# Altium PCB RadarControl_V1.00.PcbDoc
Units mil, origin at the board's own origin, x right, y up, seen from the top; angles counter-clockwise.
Board outline 6000 x 4000 mil, 2 copper layers (Top Layer, Bottom Layer); 76 components, 67 nets, 269 pads, 123 vias.
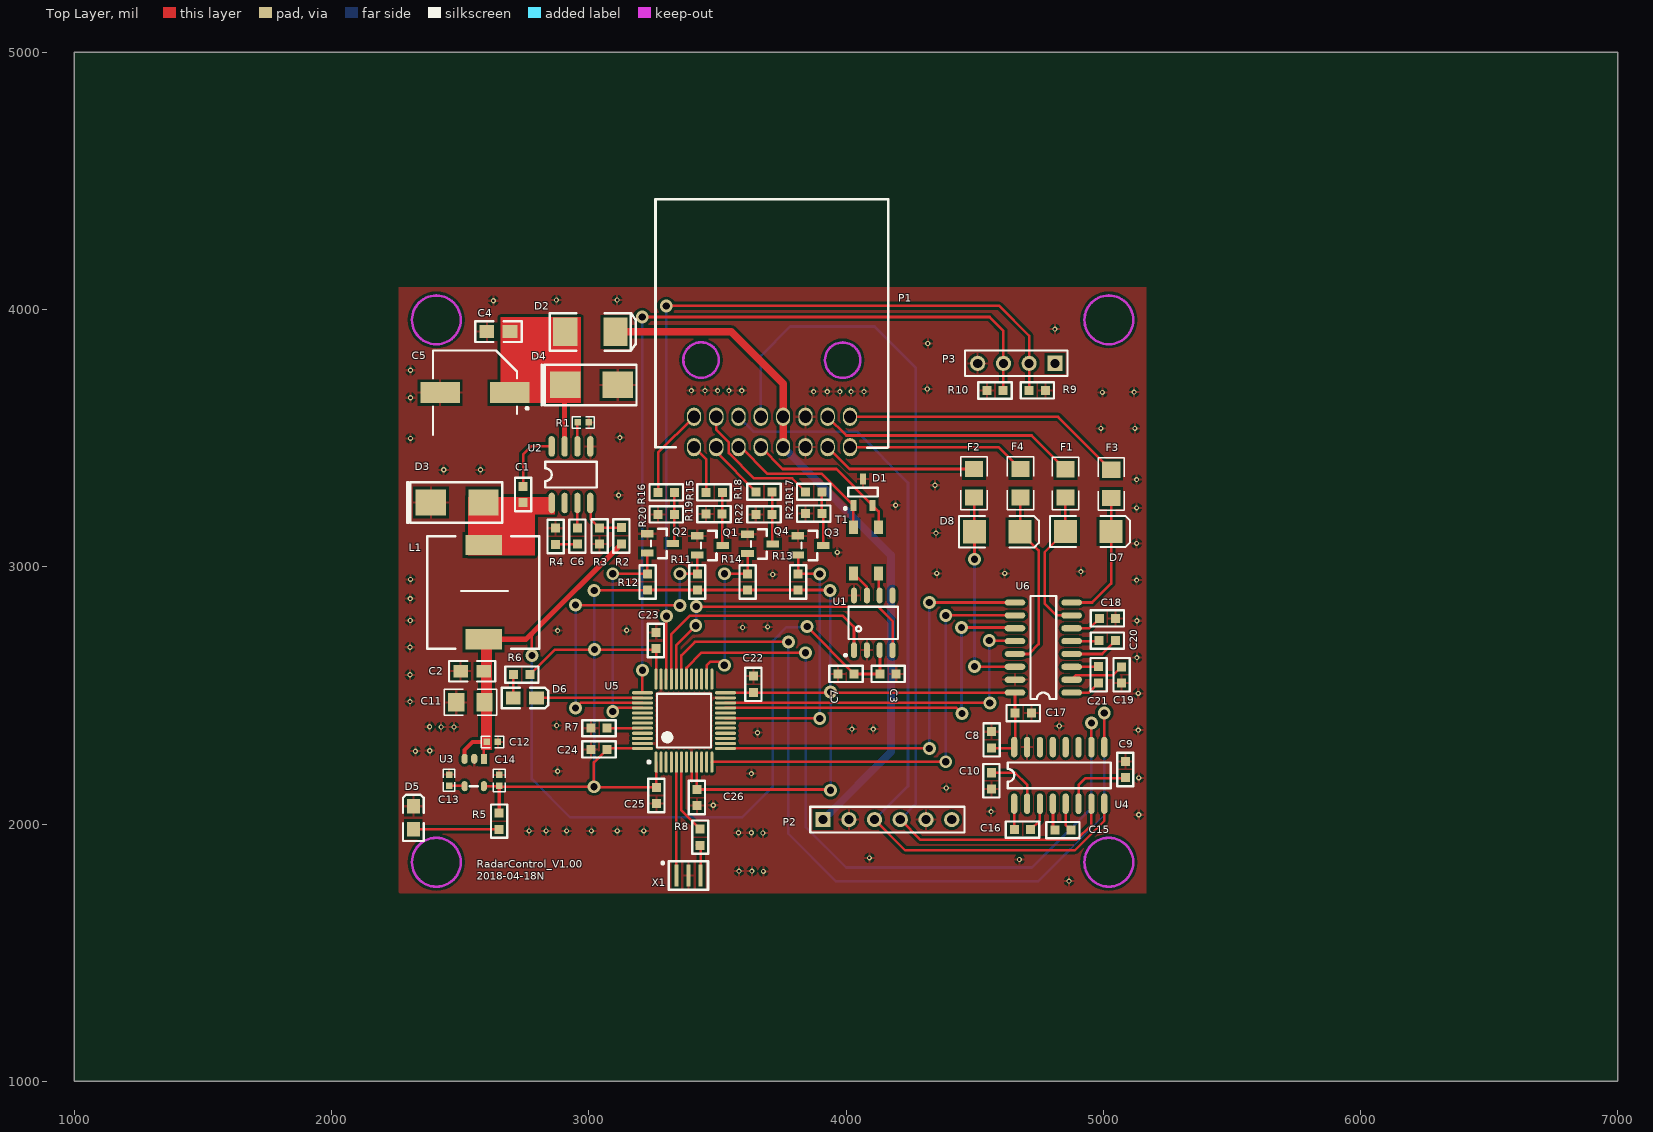
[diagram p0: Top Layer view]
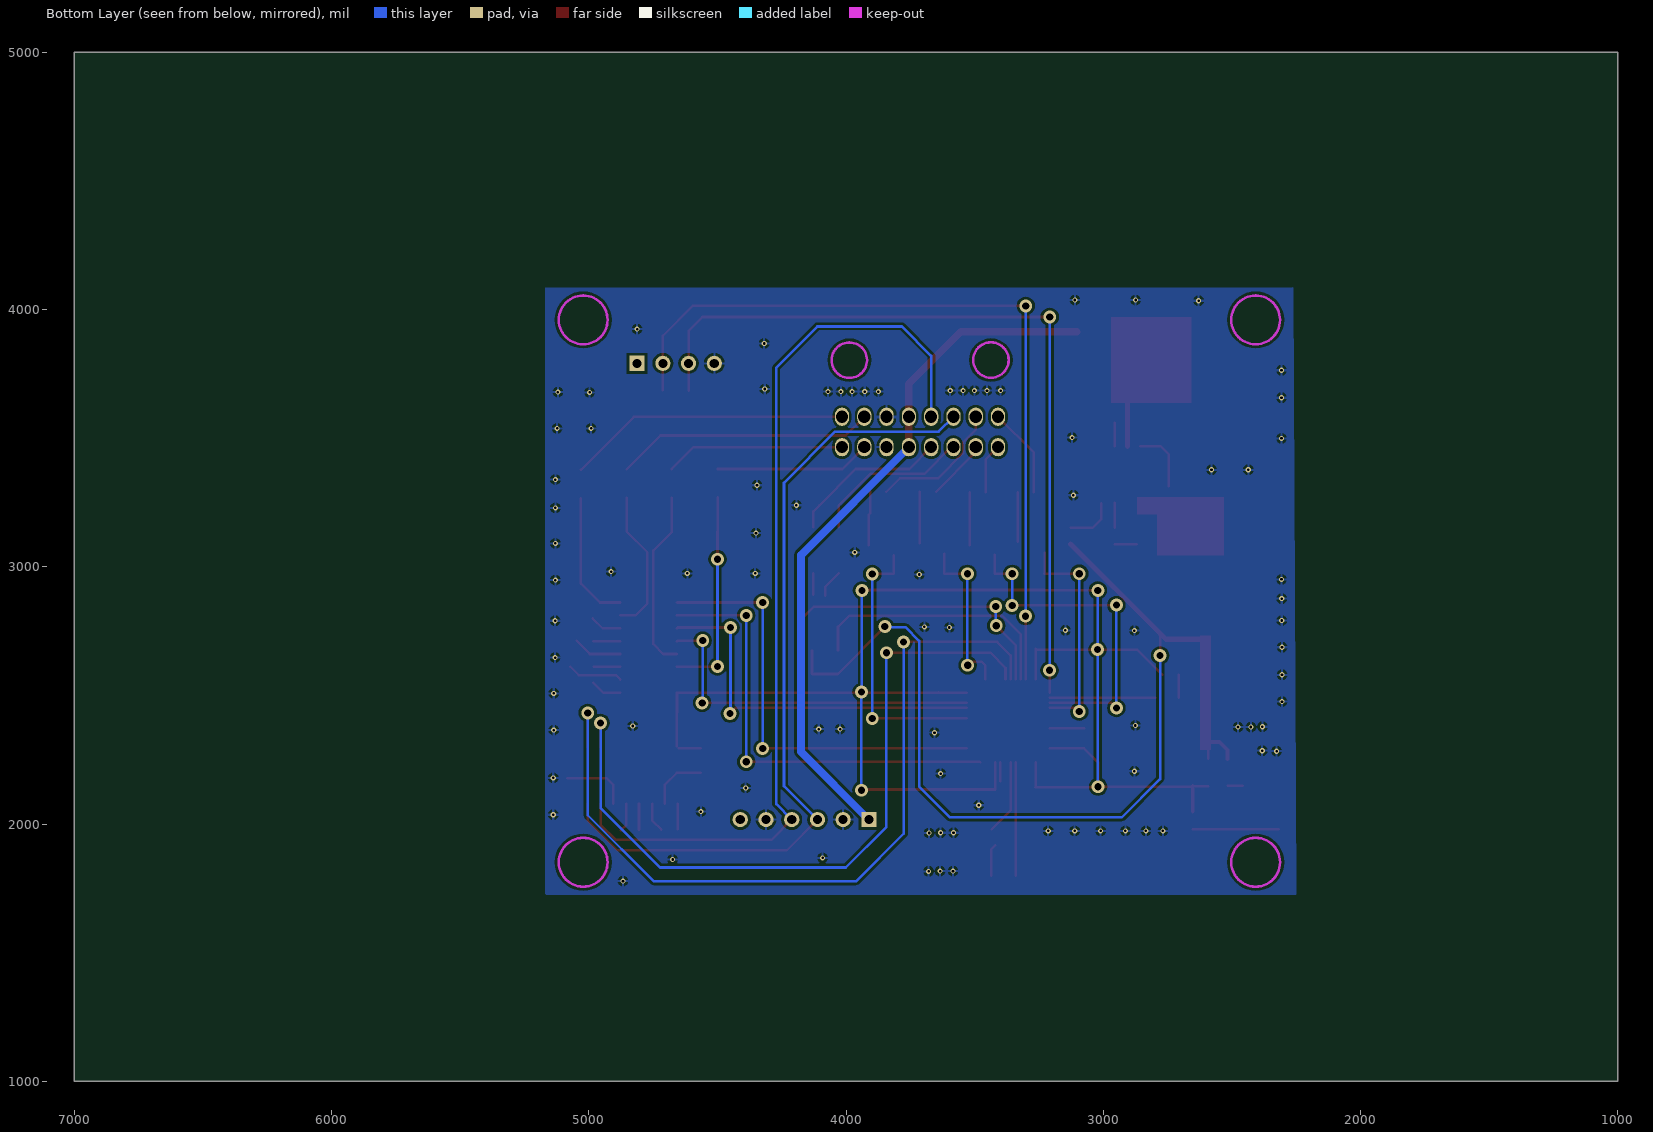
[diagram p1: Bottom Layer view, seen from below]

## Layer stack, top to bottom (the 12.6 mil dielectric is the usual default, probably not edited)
Top Solder: solder mask 0.4, Solder Resist, Dk 3.5
Top Layer: signal copper 1.4
Dielectric 1: dielectric 12.6, FR-4, Dk 4.8
Bottom Layer: signal copper 1.4
Bottom Solder: solder mask 0.4, Solder Resist, Dk 3.5

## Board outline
1000,1000 7000,1000 7000,5000 1000,5000

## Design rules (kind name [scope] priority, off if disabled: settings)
Clearance [All] p1: gap=5
MinimumSolderMaskSliver [All] p1 off: minsoldermaskwidth=10
PolygonConnect [All] p1: connectstyle=Relief reliefconductorwidth=10 reliefentries=4 polygonreliefangle="90 Angle" airgapwidth=10
RoutingVias [All] p1: holewidth=28 width=50 viastyle="Through Hole" minholewidth=28 minwidth=50 maxholewidth=28 maxwidth=50
SilkToSilkClearance [All] p1 off: silktosilkclearance=10
SilkToSolderMaskClearance [IsPad] p1 off: minsilkscreentomaskgap=10 clearancetoexposedcopper=TRUE
SolderMaskExpansion [All] p1: expansion=4
Width [All] p1: maxlimit=30 minlimit=10 preferedwidth=10
27 further rules are at their usual default settings.

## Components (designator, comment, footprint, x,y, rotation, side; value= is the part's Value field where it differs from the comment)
C1 "100nF" 0603 2749,3220 r180 top
C2 "22uF" 0805 2547,2594 r0 top
C3 "100nF" 0603 4225,2588 r270 top
C4 "10uF" 0805 2649,3914 r0 top
C5 "47uF" cap_pol_8*10.2 2558,3677 r180 top
C6 "150pF" 0603 2960,3058 r180 top
C7 "22uF/10V" 0603 3939,2579 r90 top
C8 "100nf" 0603 4570,2266 r180 top
C9 "100nf" 0603 5090,2151 r180 top
C10 "100nf" 0603 4561,2229 r0 top
C11 "22uF" 1206 2595,2473 r180 top
C12 "100nF" 0402 2519,2315 r90 top
C13 "NULL" 0402 2461,2064 r180 top
C14 "1uF" 0402 2656,2063 r180 top
C15 "100nf" 0603 4782,1972 r90 top
C16 "100nf" 0603 4625,1974 r90 top
C17 "100nf" 0603 4628,2427 r90 top
C18 "100nf" 0603 4954.95,2795 r90 top
C19 "100nf" 0603 5067,2641.05 r0 top
C20 "100nf" 0603 5077,2717 r270 top
C21 "100nf" 0603 4986,2519 r180 top
C22 "100nF" 0603 3644,2482 r180 top
C23 "100nF" 0603 3265,2652 r180 top
C24 "100nF" 0603 3101.05,2294 r270 top
C25 "100nF" 0603 3259,2172 r0 top
C26 "1uF" 0603 3416,2164 r0 top
D1 "PESD2CAN" SOT23 4068,3291 r90 top
D2 "1N4007" 6032_pol 3004,3915 r0 top
D3 "B290-13-F" B290 2386,3250 r0 top
D4 "SMAJ36CA" B290 2908,3707 r0 top
D5 "LED_POWER" 0805-LED 2318,2024 r90 top
D6 "LED0" 0805-LED 2752,2490 r0 top
D7 "SMBJ18CA" SMB 4942,3137 r0 top
D8 "SMBJ18CA" SMB 4588,3136 r0 top
F1 "SMD1206-010" 1206 4853,3379 r270 top
F2 "SMD1206-010" 1206 4498,3380 r270 top
F3 "SMD1206-010" 1206 5031,3377 r270 top
F4 "SMD1206-010" 1206 4678,3380 r270 top
L1 "22uH" 10*10Inductor 2591,2718 r0 top
P1 "1318382(16PIN)" "16pin 1318382" 4127,3483 r180 top
P2 "2.54MM-5PIN" HDR1X6 3911,2017 r0 top
P3 "2.54mm/4pin" HDR1X4 4811.97,3790.83 r180 top
Q1 "LMBT3904LT1G" LC-SOT-23(SOT-23-3) 3471,3083 r180 top
Q2 "LMBT3904LT1G" LC-SOT-23(SOT-23-3) 3277,3091 r180 top
Q3 "LMBT3904LT1G" LC-SOT-23(SOT-23-3) 3862,3083 r180 top
Q4 "LMBT3904LT1G" LC-SOT-23(SOT-23-3) 3666,3089 r180 top
R1 "200K" 0402 2872,3557 r90 top
R2 "205K" 0603 3131,3059 r180 top
R3 "40.2K" 0603 3038,3181 r0 top
R4 "100k" 0603 2875,3057 r180 top
R5 "510R" 0603 2647,2072 r0 top
R6 "2.2K" 0603 2801,2585 r270 top
R7 "10K" 0603 2979,2368 r90 top
R8 "100" 0603 3429,2010 r0 top
R9 "1K" 0603 4805,3690 r270 top
R10 "1K" 0603 4518,3681 r90 top
R11 "10K" 0603 3426,2880 r180 top
R12 "10K" 0603 3233,2880 r180 top
R13 "10K" 0603 3818,2880 r180 top
R14 "10K" 0603 3622,2880 r180 top
R15 "100k" 0603 3426.24,3284.75 r90 top
R16 "100k" 0603 3240.24,3284.75 r90 top
R17 "100k" 0603 3813.76,3287.25 r90 top
R18 "100k" 0603 3619.95,3287.25 r90 top
R19 "10K" 0603 3548.28,3208.75 r270 top
R20 "10K" 0603 3362.28,3208 r270 top
R21 "10K" 0603 3935.8,3211.25 r270 top
R22 "10K" 0603 3742,3208 r270 top
T1 "ACT45B-510-2P" ACT45B-510-2P 4127,2974 r90 top
U1 "TJA1050T" SO8 4105,2781 r90 top
U2 "MP2565DN" so-8 2856,3248 r90 top
U3 "RT9013-33GB" SOT-23-5 2553,2206 r180 top
U4 "SP3232EEN" SO-16 4654,2079 r90 top
U5 "STM32F103C8T6" STM-LQFP48_M 3370,2402 r90 top
U6 "SP3232EEN" SO-16 4877,2511 r180 top
X1 "8M smd" 8M 3340.47,1799.53 r0 top

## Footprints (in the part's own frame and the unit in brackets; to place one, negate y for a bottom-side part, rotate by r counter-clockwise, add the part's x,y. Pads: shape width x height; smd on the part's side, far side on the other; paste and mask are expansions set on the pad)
8M [mm]
  rect 0.4x2.2 smd: 1(0,0) 2(1.2,0) 3(2.4,0)
  silkscreen extent -1.45,-1.39 3.13,1.4
10*10Inductor [mm]
  rect 3.6x2 smd: 1(0,0) 2(0,9.3)
  silkscreen extent -5.55,-0.92 5.49,10.19
"16pin 1318382" [mm] "1318382"
  oval 1.4x1.8 hole 1.2: 1(2.835,-2.542) 2(5.035,-2.542) 3(7.235,-2.542) 4(9.435,-2.542) 5(11.635,-2.542) 6(13.835,-2.542) 7(16.035,-2.542) 8(18.235,-2.542) 9(2.835,0.458) 10(5.035,0.458) 11(7.235,0.458) 12(9.435,0.458) 13(11.635,0.458) 14(13.835,0.458) 15(16.035,0.458) 16(18.235,0.458)
  Keep-Out Layer circle w0.254: c3.556,-8.128 r1.75
  Keep-Out Layer circle w0.254: c17.535,-8.142 r1.75
  silkscreen extent -0.96,-24 22.04,0.51
0402 [mil]
  rect 25x25 smd: 1(3.98,-127.99) 2(3.98,-84.98)
  silkscreen extent -19,-150 26,-63
0603 [mil]
  rect 35x35 smd: 1(4.25,-92.76) 2(4.25,-29.76)
  silkscreen extent -27,-126 36,4
0805 [mil]
  rect 57x50 smd: 1(-45,0) 2(45,0)
  silkscreen extent -90,-40 90,40
0805-LED [mil]
  rect 57x50 smd: 1(-45,0) 2(45,0)
  silkscreen extent -90,-40 90,40
1206 [mm]
  rect 1.6x1.8 smd: 1(0,0) 2(2.8,0)
  silkscreen extent -1.2,-1.3 4,1.3
6032_pol [mm]
  rect 2.4x2.8 smd: 1(2.538,-0.041) 2(-2.422,-0.041)
  silkscreen extent -3.95,-1.89 4.53,1.81
ACT45B-510-2P [mm]
  rect 1.35x0.9 smd: 1(0,0) 2(4.55,0) 3(0,2.5) 4(4.55,2.5)
B290 [mm]
  rect 3x2.6 smd: 1(0,0) 2(5.2,0)
  silkscreen extent -2.34,-2 7.06,2
cap_pol_8*10.2 [mm]
  rect 3.9x2.05 smd: 1(-3.443,-0.001) 2(3.457,-0.001)
  silkscreen extent -5.27,-4.15 4.16,4.15
HDR1X4 [mm] "Connector; Header; 4 Position"
  rect 1.5x1.5 hole 0.9: 1(0,0)
  round 1.5 hole 0.9: 2(2.54,0) 3(5.08,0) 4(7.62,0)
  silkscreen extent -1.27,-1.27 8.89,1.27
HDR1X6 [mm] "Connector; Header; 6 Position"
  rect 1.5x1.5 hole 0.9: 1(0,0)
  round 1.5 hole 0.9: 2(2.54,0) 3(5.08,0) 4(7.62,0) 5(10.16,0) 6(12.7,0)
  silkscreen extent -1.27,-1.27 13.97,1.27
LC-SOT-23(SOT-23-3) [mm]
  rect 1.25x0.7 smd: 1(1.25,-0.95) 2(-1.25,0) 3(1.25,0.95)
  silkscreen extent -0.65,-1.46 0.9,1.46
SMB [mm] "DO-214-AA/SMB; 2 C-Bend Leads; Body 5.3 x 3.6 mm, inc. leads (LxW)"
  rect 2.3x2.3 smd: 1(-2.25,0) 2(2.25,0)
  silkscreen extent -3.8,-1.55 4.1,1.55
SO8 [mm]
  oval 1.55x0.6 smd: 1(-2.675,1.88) 2(-2.675,0.61) 3(-2.675,-0.66) 4(-2.675,-1.93) 5(2.725,-1.93) 6(2.725,-0.66) 7(2.725,0.61) 8(2.725,1.88)
  silkscreen extent -3.3,-2.48 1.63,2.85
so-8 [mil]
  oval 80x24 smd: 1(0,0) 2(0,-50) 3(0,-100) 4(0,-150) 5(220,-150) 6(220,-100) 7(220,-50) 8(220,0)
  silkscreen extent 60,-175 160,25
SO-16 [mil]
  oval 80x24 smd: 1(0,0) 2(0,-50) 3(0,-100) 4(0,-150) 5(0,-200) 6(0,-250) 7(0,-300) 8(0,-350) 9(220,-350) 10(220,-300) 11(220,-250) 12(220,-200) 13(220,-150) 14(220,-100) 15(220,-50) 16(220,0)
  silkscreen extent 60,-375 160,25
SOT23 [mm]
  rect 1.1x0.6 smd: 1(-1.325,1.001) 2(-1.325,-0.899) 3(1.275,0.051)
  silkscreen extent -1.75,-1.4 0.4,1.93
SOT-23-5 [mm]
  rect 0.6x1 smd: 1(-0.995,-1.201)
  oval 0.6x1 smd: 2(-0.045,-1.201) 3(0.905,-1.201) 4(0.905,1.499) 5(-0.995,1.499)
  silkscreen extent -0.4,1.5 0.4,1.5, body extent -1.5,-1.3 1.4,1.5, height 1.2
STM-LQFP48_M [mm] "QFP, 48-Leads, Body 7x7mm, Pitch 0.5mm, IPC Low Density"
  oval 2.1x0.3 smd: 1(-4.1,2.75) 2(-4.1,2.25) 3(-4.1,1.75) 4(-4.1,1.25) 5(-4.1,0.75) 6(-4.1,0.25) 7(-4.1,-0.25) 8(-4.1,-0.75) 9(-4.1,-1.25) 10(-4.1,-1.75) 11(-4.1,-2.25) 12(-4.1,-2.75) 25(4.1,-2.75) 26(4.1,-2.25) 27(4.1,-1.75) 28(4.1,-1.25) 29(4.1,-0.75) 30(4.1,-0.25) 31(4.1,0.25) 32(4.1,0.75) 33(4.1,1.25) 34(4.1,1.75) 35(4.1,2.25) 36(4.1,2.75)
  oval 0.3x2.1 smd: 13(-2.75,-4.1) 14(-2.25,-4.1) 15(-1.75,-4.1) 16(-1.25,-4.1) 17(-0.75,-4.1) 18(-0.25,-4.1) 19(0.25,-4.1) 20(0.75,-4.1) 21(1.25,-4.1) 22(1.75,-4.1) 23(2.25,-4.1) 24(2.75,-4.1) 37(2.75,4.1) 38(2.25,4.1) 39(1.75,4.1) 40(1.25,4.1) 41(0.75,4.1) 42(0.25,4.1) 43(-0.25,4.1) 44(-0.75,4.1) 45(-1.25,4.1) 46(-1.75,4.1) 47(-2.25,4.1) 48(-2.75,4.1)
  silkscreen extent -4.22,-2.65 2.65,3.57, body extent -3.5,-3.5 3.5,3.5, height 1.6

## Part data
C1 C3 C6 C7 C8 C9 C10 C11 C13 C15 C16 C17 C18 C19 C20 C21 C22 C23 C24 C25 C26: library part Cap, "Capacitor"
C2 C4: library part Cap, "Capacitor,50V"
C5: library part "Cap Pol1", "Polarized Capacitor (Radial)"
C12: library part Cap, "Capacitor 5V"
C14: library part Cap, "Capacitor 3V3"
D1: library part PESD1CAN
D2 D4: library part "Diode 1N4007", "1 Amp General Purpose Rectifier"
D3: library part Diode, "Default Diode"
D5: library part LED0, "Typical INFRARED GaAs LED"
D6: "green LED"
D7 D8: library part "D Zener", "Zener Diode"
F1 F2 F3 F4: library part "Fuse 2", "Fuse"
L1: library part Inductor, "Inductor, 1A"
P1: library part 16PIN
P2: library part "Header 5", "Header, 5-Pin"
P3: library part "Header 4", "Header, 4-Pin"
Q1 Q2 Q3 Q4: library part 2N3904, "NPN General Purpose Amplifier"
R1 R2 R3 R4 R5 R6 R7 R8 R9 R10 R11 R12 R13 R14 R15 R16 R17 R18 R19 R20 R21 R22: library part Res1, "Resistor"
T1: library part "Trans Eq", "Transformer (Equivalent Circuit Model)"
U1: "CAN Tranceiver"
U2: library part MP1584, "DCDC 4.5V~28V input 1.8V ~5V output low power"
U3: library part RT9193
U4 U6: library part MAX202
U5: "ARM Cortex-M3 32-bit MCU, 64 KB Flash, 20 KB Internal RAM, 37 I/Os, 48-pin LQFP, -40 to 85 degC, Tray"

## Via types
v1: diameter 20, hole 10, Top Layer to Bottom Layer, 85 vias
v2: diameter 50, hole 28, Top Layer to Bottom Layer, 38 vias

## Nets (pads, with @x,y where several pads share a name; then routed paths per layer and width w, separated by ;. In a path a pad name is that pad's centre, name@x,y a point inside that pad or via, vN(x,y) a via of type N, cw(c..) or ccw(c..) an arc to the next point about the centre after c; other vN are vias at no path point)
24V: D2.1 P1.4 P1.12 P2.1 | length 2712.8
  Top Layer w30: D2.1 3553.63,3913.37 3755.54,3711.46 P1.4 P1.12
  Bottom Layer w30: P1.12 4175,3045.51 4175,2281 P2.1
232_RXD1: P1.6 P2.3 U4.8 | length 3184.5
  Top Layer w10: P2.3 4230,1898 4890,1898 5004,2012 U4.8
  Bottom Layer w10: P1.6 3640.39,3525 4042,3525 4241,3326 4241,2147 P2.3
232_RXD2: F3.1 P1.1 | length 1101
  Top Layer w10: P1.1 4824.92,3583.08 F3.1
232_RXD3: F4.1 P1.9 | length 697.8
  Top Layer w10: P1.9 4593.03,3464.97 F4.1
232_TXD1: P1.5 P2.4 U4.7 | length 3616.5
  Top Layer w10: P2.4 4290,1938 4895,1938 4954,1997 U4.7
  Bottom Layer w10: P1.5 3668.93,3819.93 3783,3934 4111,3934 4271,3774 4271,2077 P2.4
232_TXD2: F1.1 P1.2 | length 1008.8
  Top Layer w10: P1.2 4001.45,3510.4 4721.6,3510.4 F1.1
232_TXD3: F2.1 P1.10 | length 604.4
  Top Layer w10: P1.10 4013.74,3380 F2.1
A5V0: C2.2 C3.1 C7.1 C11.1 C12.2 L1.1 R2.2 U1.3 U3.1 U3.3 | length 3683.6
  Top Layer w10: U3.1 C12.2@2592.17,2318.98 ; C12.2@2592.17,2325.02 C12.2@2592.17,2318.98 ; C12.2 C12.2@2592.17,2318.98 ; v2(2779,2655) 2779,2741.02 2784.49,2746.51 ; v2@3848,2767 C7.1 C3.1@4131.75,2583.25 ; C3.1 U1.3@4132.24,2674.46
  Top Layer w15: U3.3 2517.37,2288.37 2547.98,2318.98 C12.2@2592.17,2318.98
  Top Layer w20: L1.1 2755.98,2718 2779,2741.02 ; 2784.49,2746.51 R2.2
  Bottom Layer w10: v2@2778,2655 v2(2779,2655) 2779,2175 2928,2026 3596,2026 3716,2146 3716,2712 3769,2765 3846,2765 v2(3849,2768)
BACKDOOR: P1.16 R15.2 | length 195.4
  Top Layer w10: P1.16 3456,3418.06 R15.2
CAN_H: D1.1 P1.14 T1.4 | length 625.6
  Top Layer w10: P1.14 3591.03,3464.97 3695,3361 3906.42,3361 D1.1 T1.4@4028.6,3153.16
CAN_L: D1.2 P1.13 T1.2 | length 623.6
  Top Layer w10: P1.13 3753.9,3380 3962.22,3380 D1.2 4127,3215.22 T1.2
CAN_RX: U1.4 U5.32 | length 1210.4
  Top Layer w10: U5.32 3340.47,2695.47 v2(3416,2771) ; v2(3418,2845) 4125,2845 4181,2789 U1.4
  Bottom Layer w10: v2@3418,2773 v2(3418,2845)
CAN_TX: U1.1 U5.33 | length 1022.2
  Top Layer w10: U5.33 3320.79,2737.79 3392,2809 3988,2809 4031,2766 U1.1
D3V3: C8.2 C14.2 C17.2 C22.2 C23.2 C24.2 C25.2 C26.2 R5.2 R6.2 R11.2 R12.2 R13.2 R14.2 U3.5 U4.16 U5.1 U5.9 U5.24 U5.36 U5.48 U6.16 | length 6321
  Top Layer w10: U3.5 2651.03,2146.98 C14.2 ; C14.2@2653.01,2145 2655.01,2147 2657.01,2145 v2(3020,2145) 3020,2239.73 3074,2293.73 U5.48 ; R6.2 2868.49,2678 C23.2@3260.75,2678 ; v2@3020,2142.24 C25.2@3262.24,2142.24 ; v2(3021,2908) 3226.98,2908 R12.2 R14.2 R13.2 v2@3936.24,2909.76 ; U5.36 C23.2@3261.73,2681.76 ; U5.1@3262.24,2240.08 C25.2@3262.24,2142.24 ; C25.2 C25.2@3262.24,2142.24 ; C26.2@3419.21,2134.24 U5.9 ; C26.2 v2@3940,2134.24 ; U5.24 C22.2@3638.25,2510.27 ; C22.2 3640.51,2511 U6.16@4656,2511 ; C8.2@4565.75,2295.24 U4.16@4650.24,2295.24 ; C17.2@4657,2432.02 U6.16 ; U4.16@4657.76,2302.76 C17.2
  Top Layer w15: R5.2@2652.02,2048.24 C14.2
  Bottom Layer w10: v2@3021,2145 v2(3021,2908) ; v2@3938,2513 v2(3938,2908) ; v2(3940,2131) v2(3940,2513)
  other v2: 3022,2678
DGND: C2.1 C3.2 C4.1 C5.2 C7.2 C8.1 C9.1 C10.1 C11.2 C12.1 C13.1 C14.1 C17.1 C18.1 C19.1 C22.1 C23.1 C24.1 C25.1 C26.1 D1.3 D3.1 D4.2 D5.2 P1.3 P1.11 P2.2 P2.5 P3.4 Q1.1 Q2.1 Q3.1 Q4.1 R1.1 R3.1 R4.1 R7.2 R9.2 R10.2 R19.1 R20.1 R21.1 R22.1 U1.2 U1.8 U2.5 U3.2 U4.15 U5.8 U5.23 U5.35 U5.47 U6.15 X1.2 | length 74.1
  Top Layer w10: 3399.53,2166.53 U5.8
  other v1: 4867,1778 3679,1816 3584,1817 3634,1817 4674,1862 4091,1868 3677,1965 3582,1966 3632,1966 2768,1973 2834,1973 2914,1973 3010,1973 3111,1973 3214,1973 5138,2036 4564,2048 3484,2073 4390,2140 5138,2179 3632,2196 2879,2205 2326,2283 2382,2285 3656,2355 5136,2365 4023,2369 4106,2369 2426,2377 2476,2377 2381,2378 4829,2381 2875,2383 2305,2476 5136,2508 2305,2580 5131,2647 2305,2687 2879,2752 3147,2753 3598,2764 3695,2766 5131,2790 2306,2791 2306,2876 5130,2948 2307,2951 3715,2970 4353,2974 4617,2974 4913,2981 3966,3056 5130,3091 4350,3131 5130,3229 4193,3239 3116,3278 4346,3317 5130,3339 2436,3377 2579,3377 2307,3499 3121,3502 4991,3538 5123,3538 2307,3657 4997,3678 5120,3679 3874,3681 3927,3681 3976,3681 4020,3681 4070,3681 3399,3685 3452,3685 3501,3685 3545,3685 3595,3685 4316,3691 2307,3764 4318,3868 4812,3924 2629,4034 2874,4037 3110,4037
FRONTDOOR: P1.8 R16.2 | length 351.7
  Top Layer w10: R16.2 3270,3443.99 P1.8
NetC1_1: C1.1 U2.8 | length 249
  Top Layer w10: C1.1 2744.75,3436.75 2777,3469 2855,3469 U2.8
NetC1_2: C1.2 D3.2 L1.2 U2.1
NetC4_2: C4.2 C5.1 D2.2 D4.1 U2.7 | length 237
  Top Layer w20: U2.7 D4.1@2906,3705
NetC6_1: C6.1 U2.3 | length 97
  Top Layer w10: C6.1@2956,3151.01 U2.3
NetC6_2: C6.2 R4.2 | length 84
  Top Layer w10: R4.2 C6.2@2954.75,3086.76
NetC9_2: C9.2 U4.6 | length 263.1
  Top Layer w10: U4.6 4904,2151 4931.25,2178.25 C9.2@5083.76,2178.25
NetC10_2: C10.2 U4.2 | length 231.9
  Top Layer w10: C10.2 4657.76,2199.24 4704,2153 U4.2
NetC13_2: C13.2 U3.4 | length 58.4
  Top Layer w10: C13.2 U3.4@2515.38,2148.98
NetC15_1: C15.1 U4.5 | length 111.3
  Top Layer w10: U4.5 4854,1997.01 C15.1
NetC15_2: C15.2 U4.4 | length 100
  Top Layer w10: C15.2@4804.76,1978.25 U4.4@4804.76,2078.24
NetC16_1: C16.1 U4.3 | length 115.8
  Top Layer w10: C16.1 4754,2014.5 U4.3
NetC16_2: C16.2 U4.1 | length 100
  Top Layer w10: C16.2@4654,1979.02 U4.1
NetC18_2: C18.2 U6.6 | length 123.6
  Top Layer w10: U6.6 4946.46,2761 C18.2
NetC19_2: C19.2 U6.2 | length 215.1
  Top Layer w10: U6.2 4895,2579 5038.97,2579 C19.2
NetC20_1: C20.1 U6.5 | length 105.5
  Top Layer w10: U6.5 C20.1@4982.5,2711
NetC20_2: C20.2 U6.4 | length 191.7
  Top Layer w10: U6.4 4995.49,2661 C20.2
NetC21_1: C21.1 U6.3 | length 104
  Top Layer w10: U6.3 C21.1@4980.99,2611
NetC21_2: C21.2 U6.1 | length 120.4
  Top Layer w10: U6.1 4943.98,2511 C21.2
NetD5_1: D5.1 R5.1 | length 333
  Top Layer w10: D5.1 R5.1@2651.01,1979
NetD6_1: D6.1 R6.1 | length 90.7
  Top Layer w10: D6.1 R6.1@2707,2580.75
NetD6_2: D6.2 U5.38 | length 411
  Top Layer w10: D6.2 U5.38@3208,2490
NetQ1_2: Q1.2 R15.1 R19.2 | length 204.8
  Top Layer w10: Q1.2@3518.99,3084.22 R15.1
NetQ2_2: Q2.2 R16.1 R20.2 | length 191.2
  Top Layer w10: Q2.2@3332.99,3097.78 R16.1
NetQ3_2: Q3.2 R17.1 R21.2 | length 203.8
  Top Layer w10: R21.2@3906.51,3207.47 R17.1 ; Q3.2 R21.2@3911.21,3202.77
NetQ4_2: Q4.2 R18.1 R22.2 | length 200
  Top Layer w10: Q4.2@3712.71,3091.5 R18.1
NetR1_2: R1.2 U2.6 | length 92
  Top Layer w10: U2.6 R1.2@2956,3560
NetR2_1: R2.1 R3.2 U2.4 | length 193.7
  Top Layer w10: U2.4@3007.49,3246.51 3007.49,3186 R3.2 R2.1@3126.23,3151.24
NetR7_1: R7.1 U5.44 | length 135
  Top Layer w10: R7.1@3073.54,2372.47 U5.44
NetR8_1: R8.1 X1.3 | length 123.8
  Top Layer w10: R8.1@3420.25,1917.24 3434.96,1902.54 X1.3
NetR8_2: R8.2 U5.6 | length 290.8
  Top Layer w10: U5.6 3360.16,2052.84 R8.2@3433.01,1979.99
NetT1_1: T1.1 U1.6 | length 81.7
  Top Layer w10: U1.6@4127,2892.3 T1.1
NetT1_3: T1.3 U1.7 | length 107.4
  Top Layer w10: T1.3 4081,2921.57 U1.7
NetU5_5: U5.5 X1.1 | length 441.1
  Top Layer w10: X1.1 U5.5
PA8: Q2.3 R12.1 U5.40 | length 872.9
  Top Layer w10: v2(3093,2437) 3107.21,2451.21 U5.40 ; v2(3093,2973) R12.1@3228.5,2973 ; R12.1@3227.79,2973.72 Q2.3
  Bottom Layer w10: v2(3093,2437) v2(3093,2973)
PB13: Q3.3 R13.1 U5.19 | length 1082.1
  Top Layer w10: U5.19 v2@3896.16,2411.84 ; Q3.3@3813.75,3044.64 R13.1 v2@3897.24,2972.76
  Bottom Layer w10: v2(3898,2410) v2(3898,2972)
PB14: Q4.3 R14.1 U5.26 | length 644.9
  Top Layer w10: U5.26 3458.58,2615.58 3474,2631 v2@3523,2631 ; v2(3528.24,2972.76) R14.1 Q4.3@3617.75,3050.64
  Bottom Layer w10: v2@3528.24,2618.24 v2(3528.24,2972.76)
  other v2: 3527,2617
PB15: Q1.3 R11.1 U5.39 | length 1375.9
  Top Layer w10: v2(2949,2451) 2970,2472 3208.58,2472 U5.39 ; v2(2949,2851) v2@3354,2851 ; v2(3354,2972.76) R11.1 ; R11.1@3421.79,2972.76 Q1.3
  Bottom Layer w10: v2(2949,2451) v2(2949,2851) v2@2949,2855 ; v2@3370.76,2852.24 v2@3374,2849 ; v2@3373.49,2849 v2(3354,2849) 3353,2850 3353,2951.76 v2@3374,2972.76
REVERSE: P1.7 R17.2 | length 522.8
  Top Layer w10: P1.7 3495.7,3532.3 3544.76,3483.24 3544.76,3441.54 3642.29,3344 3791.02,3344 R17.2
RT-IN1: D8.2 F4.2 U6.13 | length 707.1
  Top Layer w10: U6.13 4711,2661 4749,2699 4749,3063.58 D8.2 F4.2@4676.58,3268.35
RT-IN2: D7.2 F3.2 U6.8 | length 515.8
  Top Layer w10: U6.8 4957,2861 5030.58,2934.58 D7.2 F3.2@5030.58,3266.35
RT-OUT1: D8.1 F2.2 U6.14 | length 813.3
  Top Layer w10: D8.1@4498,3137.42 F2.2 ; v2(4499.42,3029.42) D8.1 ; v2(4500,2612) U6.14@4657,2612
  Bottom Layer w10: v2@4499.42,2612 v2(4499.42,3029.42)
RT-OUT2: D7.1 F1.2 U6.7 | length 568.8
  Top Layer w10: F1.2 4853,3137.42 4772,3056.42 4772,2858 4819,2811 U6.7
SPEED: P1.15 R18.2 | length 237.3
  Top Layer w10: P1.15 3495.7,3445.52 R18.2
SWCLK: P3.3 R10.1 U5.37 | length 3119.1
  Top Layer w10: v2(3208,3971) 4558,3971 4611.97,3917.03 P3.3 R10.1@4611.97,3685.25 ; U5.37 v2(3208.58,2597.58)
  Bottom Layer w10: v2(3208,3971) 3208,2598.17 v2(3208.58,2597.58)
SWDIO: P3.2 R9.1 U5.34 | length 3121.9
  Top Layer w10: v2(3301,4014) 4596,4014 4711.97,3898.03 P3.2 R9.1@4711.97,3685.75 ; U5.34 v2@3301.1,2808
  Bottom Layer w10: v2(3302,2808) v2@3302,4014
USART1_RX: U4.9 U5.31 | length 3218.4
  Top Layer w10: U5.31 3360.16,2655.16 3413,2708 v2(3776,2708) ; U4.9 v2(5004,2432)
  Bottom Layer w10: 3775,1964 3962,1777 4747,1777 5004,2034 v2(5004,2432) ; 3776,1963 v2(3776,2708)
USART1_TX: U4.10 U5.30 | length 2905.2
  Top Layer w10: U5.30 3379.84,2606.84 3439,2666 v2(3843,2666) ; U4.10 v2(4954,2393)
  Bottom Layer w10: v2(3843,2666) 3843,1989 4001,1831 4723,1831 4954,2062 v2(4954,2393)
USART2_RX: U5.13 U6.9 | length 1676.6
  Top Layer w10: U5.13 v2@4308,2293.73 ; v2(4324,2861) U6.9
  Bottom Layer w10: v2(4324,2294) v2(4324,2861)
USART2_TX: U5.12 U6.10 | length 1745.3
  Top Layer w10: U5.12 3479.68,2242 v2(4388,2242) ; v2@4391,2811 U6.10
  Bottom Layer w10: v2(4388,2242) v2(4388,2811)
USART3_RX: U5.22 U6.12 | length 1368.5
  Top Layer w10: U5.22 v2(4559.1,2470.9) ; v2(4557,2713) 4655,2713 U6.12
  Bottom Layer w10: v2@4557,2473 v2(4557,2713)
USART3_TX: U5.21 U6.11 | length 1473.9
  Top Layer w10: U5.21 4428.79,2451.21 v2(4451,2429) ; v2(4449,2764) 4654,2764 U6.11
  Bottom Layer w10: v2(4449,2764) 4449,2431 v2(4451,2429)
pads on no net: P2.6 P3.1 U1.5 U2.2 U4.11 U4.12 U4.13 U4.14 U5.2 U5.3 U5.4 U5.7 U5.10 U5.11 U5.14 U5.15 U5.16 U5.17 U5.18 U5.20 U5.25 U5.27 U5.28 U5.29 U5.41 U5.42 U5.43 U5.45 U5.46

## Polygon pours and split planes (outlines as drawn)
DGND on Top Layer "Top Layer-DGND" (solid, remove dead copper, pour order 0): 2261,4087 5167,4087 5167,1730 2266,1730 2261,1735
DGND on Bottom Layer "Bottom Layer-DGND" (solid, remove dead copper, pour order 2): 2261,4092 2269,4084 5169,4084 5169,1728 5165,1724 2249,1724

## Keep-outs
Keep-Out Layer:
  circle w10: c2407.42,1851.31 r94.87
  circle w10: c5021.59,1851.31 r94.87
  circle w10: c5021.59,3959.57 r94.87
  circle w10: c2407.42,3959.57 r94.87

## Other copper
Top Layer:
  rectangle net NetC4_2: 2657,3637 2969,3971
  rectangle net NetC1_2: 2590,3076 2590.72,3250
  rectangle net NetC1_2: 2530,3044 2791,3272
  rectangle net NetC1_2: 2791,3204 2869,3272
  rectangle net A5V0: 2581,2287 2624,2732

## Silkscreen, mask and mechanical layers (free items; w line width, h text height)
Top Overlay:
  text "RadarControl_V1.00 / 2018-04-18N" at 2565,1784 h30
Mechanical 1:
  circle w0.5: c2407.42,3959.57 r82.68
  circle w0.5: c5021.59,3959.57 r82.68
  circle w0.5: c2407.42,1851.31 r82.68
  circle w0.5: c5021.59,1851.31 r82.68
  lines w0.5: 2260.75,1759.08 ccw(c2296.08,1759.08) 2296.08,1723.75 5132.45,1723.75 ccw(c5132.45,1757.59) 5166.28,1757.59 5166.28,4046.74 ccw(c5126.91,4046.74) 5126.91,4086.11 2300.12,4086.11 ccw(c2300.12,4046.74) 2260.75,4046.74 2260.75,1759.08
Mechanical 10:
  lines w0.5: 5011.59,1851.31 5031.59,1851.31 5011.59,1851.31 ; 5021.59,1841.31 5021.59,1861.31 5021.59,1841.31
Mechanical 16:
  lines w0.5: 2265.69,1725.32 2265.69,4085.56
Mechanical 30:
  lines w0.5: 4486.99,2297.78 4486.99,2397.78 4882.65,2397.78 4882.65,2297.78 4486.99,2297.78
